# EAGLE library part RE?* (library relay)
SMALL MICROWAVE RELAYS FOR BROADCASTING INDUSTRY NAiS Source: http://www.mew-europe.com/.. en_ds_61310_0000.pdf
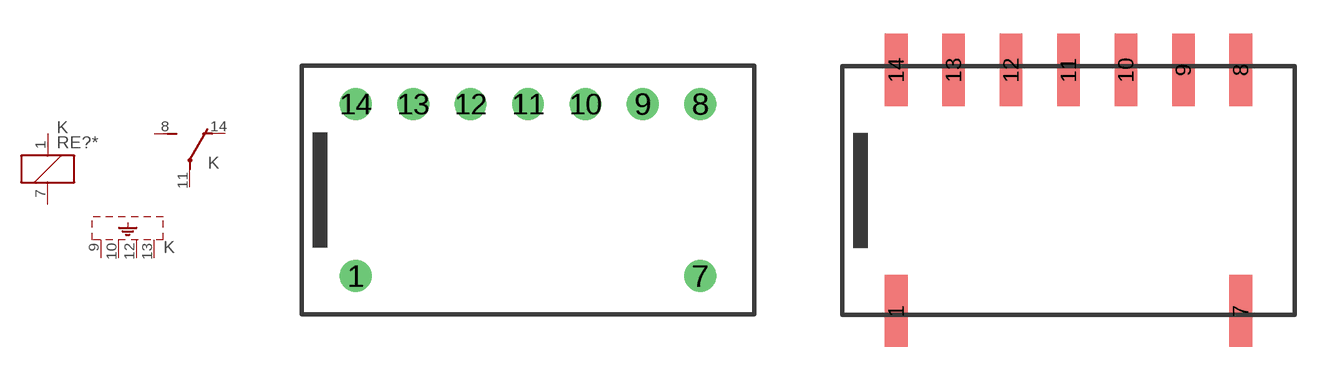
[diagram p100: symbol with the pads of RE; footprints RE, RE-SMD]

Designator prefix K; gates 1=K 2=U S1=SHIELD-4

## RE1303 (MF: AROMAT/ MATSUSHITA; MPN: ARE1303; OC_FARNELL: 1448347; OC_NEWARK: 64K3078), RE134H (MPN: ARE134H; OC_FARNELL: 3772998; OC_NEWARK: 13P1246), RE1306 (MPN: ARE1306; OC_FARNELL: unknown; OC_NEWARK: 11N2917), RE1309 (MPN: ARE1309; OC_FARNELL: unknown; OC_NEWARK: 95M8248), RE1312 (MPN: ARE1312; OC_FARNELL: 3773000; OC_NEWARK: 13P1245), RE1324 (MPN: ARE1324; OC_FARNELL: unknown; OC_NEWARK: 11N2919)  [RE]
1  1:1  pas
7  1:2  pas
8  2:S  pas
9  S1:SH  pas
10  S1:SH  pas
11  2:P  pas
12  S1:SH  pas
13  S1:SH  pas
14  2:O  pas

## RE13A03 (MPN: ARE13A03; OC_FARNELL: unknown; OC_NEWARK: 71M0380), RE13A4H (MPN: ARE13A4H; OC_FARNELL: 3773024; OC_NEWARK: 11N2913), RE13A06 (MPN: ARE13A06; OC_FARNELL: unknown; OC_NEWARK: 11N2902), RE13A09 (MPN: ARE13A09; OC_FARNELL: unknown; OC_NEWARK: 11N2904), RE13A12 (MPN: ARE13A12; OC_FARNELL: 3773036; OC_NEWARK: 13P1241), RE13A24 (MPN: ARE13A24; OC_FARNELL: unknown; OC_NEWARK: 11N2909)  [RE-SMD]
Pads as for RE

## Footprint RE (pad centres in mm)
SMALL MICROWAVE RELAYS FOR BROADCASTING INDUSTRY NAiS Source: http://www.mew-europe.com/.. en_ds_61310_0000.pdf
drill 0.9 round: 1 -7.62,-3.81; 7 7.62,-3.81; 8 7.62,3.81; 9 5.08,3.81; 10 2.54,3.81; 11 0,3.81; 12 -2.54,3.81; 13 -5.08,3.81; 14 -7.62,3.81

## Footprint RE-SMD (pad centres in mm)
SMALL MICROWAVE RELAYS FOR BROADCASTING INDUSTRY NAiS Source: http://www.mew-europe.com/.. en_ds_61310_0000.pdf
smd 1 x 3.2: 1 -7.62,-5.334; 7 7.62,-5.334; 8 7.62,5.334; 9 5.08,5.334; 10 2.54,5.334; 11 0,5.334; 12 -2.54,5.334; 13 -5.08,5.334; 14 -7.62,5.334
